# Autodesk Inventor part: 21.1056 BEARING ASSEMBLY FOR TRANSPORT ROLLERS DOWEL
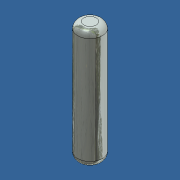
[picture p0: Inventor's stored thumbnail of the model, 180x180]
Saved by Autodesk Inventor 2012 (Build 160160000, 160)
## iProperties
Created: 2007-07
Part Number: 21.1056 BEARING ASSEMBLY FOR TRANSPORT ROLLERS DOWEL
Document SubType Name: Modeling
Designer: Andy Moles
Material: Steel
Mass: 14.8511 g
Surface Area: 10.1892 cm^2
Volume: 1.89187 cm^3
Density: 7.85 g/cm^3
Author: Andy Moles
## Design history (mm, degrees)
sketch "Sketch1"
  geometry: C1 r 4 at (0, 0); 1 further point
  constraints: 1 centre point, 1 coincident
  dimensions: "d0" = 8 diameter of C1
extrude "Extrusion1" new body sketch "Sketch1" stored distance "d1" = 38.4; taper "d2" = 0 deg
fillet "Fillet1" dims "d3" = 2
body "Solid1"
